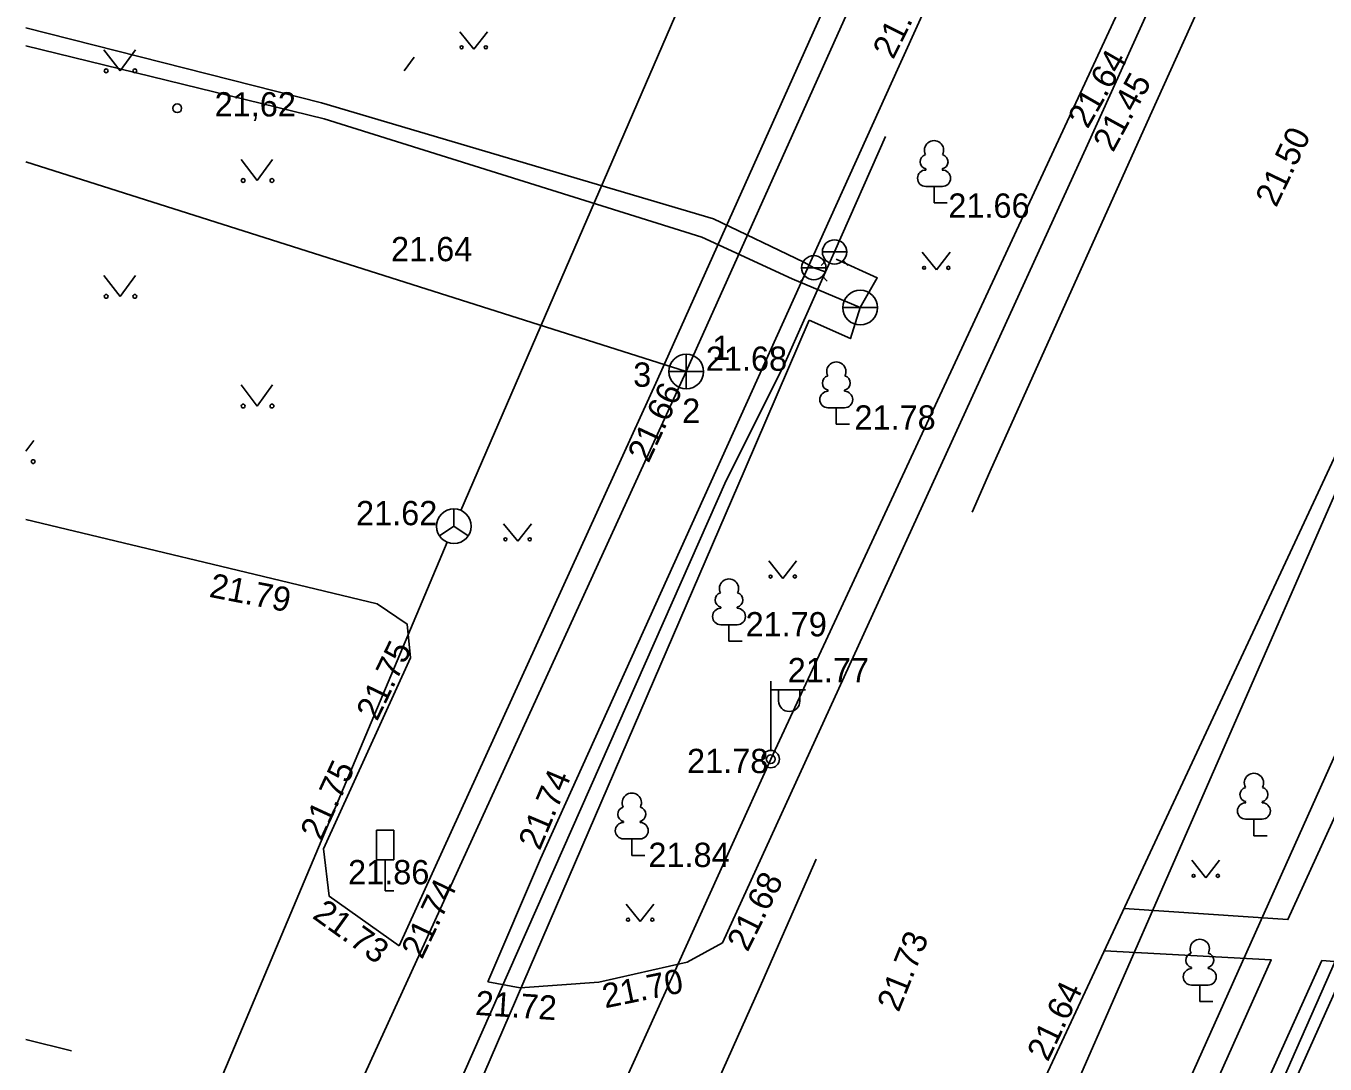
# Model space of a CAD drawing. Extents: x 714391 to 714584, y 6589993 to 6590151.
# Drawn here: x 714390.65 to 714428.09, y 6590022.48 to 6590052.39 of the extents above; entities that cross this region are included whole.
import ezdxf

# ---------------------------------------------------------------- set-up
doc = ezdxf.new("R2010")
doc.units = 0
for name, color, linetype in [('ABIJOONIS', 7, 'Continuous'), ('HALJASTUS', 7, 'Continuous'), ('HOONE', 7, 'Continuous'), ('KKAEV', 7, 'Continuous'), ('KORGUS', 7, 'Continuous'), ('KPKAABEL', 7, 'Continuous'), ('KTRASS', 7, 'Continuous'), ('LIIKLUS', 7, 'Continuous'), ('MPKAABEL', 7, 'Continuous'), ('POST', 7, 'Continuous'), ('PUU', 7, 'Continuous'), ('SIKAEV', 7, 'Continuous'), ('SITRASS', 7, 'Continuous'), ('SKTRASS', 7, 'Continuous'), ('TEE', 7, 'Continuous'), ('TORU NR', 7, 'Continuous'), ('VKAEV', 7, 'Continuous'), ('VTRASS', 7, 'Continuous'), ('По умолчанию', 7, 'Continuous'), ('Слой 1', 7, 'Continuous')]:
    doc.layers.add(name, color=color, linetype=linetype)

msp = doc.modelspace()

# ---------------------------------------------------------------- linework, layer by layer
at = {"layer": 'ABIJOONIS'}
for points in [[(714426.529, 6590057.51), (714423.049, 6590049.81), (714418.429, 6590039.54), (714417.917, 6590038.38)], [(714413.426, 6590028.381), (714411.78, 6590024.65), (714403.97, 6590007.22), (714397.447, 6589992.711)]]:
    msp.add_lwpolyline(points, dxfattribs=at)
at = {"layer": 'HALJASTUS'}
for p, q in [((714403.151, 6590052.228), (714403.556, 6590051.723)), ((714403.556, 6590051.723), (714403.951, 6590052.228)), ((714392.897, 6590051.707), (714393.36, 6590051.1)), ((714393.36, 6590051.1), (714393.806, 6590051.707)), ((714396.847, 6590048.547), (714397.31, 6590047.94)), ((714397.31, 6590047.94), (714397.756, 6590048.547)), ((714416.483, 6590045.873), (714416.888, 6590045.368)), ((714416.888, 6590045.368), (714417.283, 6590045.873)), ((714392.897, 6590045.207), (714393.36, 6590044.6)), ((714393.36, 6590044.6), (714393.806, 6590045.207)), ((714396.847, 6590042.047), (714397.31, 6590041.44)), ((714397.31, 6590041.44), (714397.756, 6590042.047)), ((714390.649, 6590040.139), (714390.876, 6590040.447)), ((714404.416, 6590038.05), (714404.821, 6590037.545)), ((714404.821, 6590037.545), (714405.216, 6590038.05)), ((714412.058, 6590036.978), (714412.463, 6590036.473)), ((714412.463, 6590036.473), (714412.858, 6590036.978)), ((714424.249, 6590028.353), (714424.654, 6590027.848)), ((714424.654, 6590027.848), (714425.049, 6590028.353)), ((714407.949, 6590027.089), (714408.354, 6590026.584)), ((714408.354, 6590026.584), (714408.749, 6590027.089))]:
    msp.add_line(p, q, dxfattribs=at)
for centre, radius in [((714403.203, 6590051.778), 0.0428), ((714403.903, 6590051.778), 0.0452), ((714392.959, 6590051.1), 0.055), ((714393.788, 6590051.1), 0.055), ((714396.909, 6590047.94), 0.055), ((714397.738, 6590047.94), 0.055), ((714416.535, 6590045.423), 0.0428), ((714417.235, 6590045.423), 0.0452), ((714392.959, 6590044.6), 0.055), ((714393.788, 6590044.6), 0.055), ((714396.909, 6590041.44), 0.055), ((714397.738, 6590041.44), 0.055), ((714390.858, 6590039.84), 0.055), ((714404.468, 6590037.6), 0.0428), ((714405.168, 6590037.6), 0.0452), ((714412.11, 6590036.528), 0.0428), ((714412.81, 6590036.528), 0.0452), ((714424.301, 6590027.903), 0.0428), ((714425.001, 6590027.903), 0.0452), ((714408.001, 6590026.639), 0.0428), ((714408.701, 6590026.639), 0.0452)]:
    msp.add_circle(centre, radius, dxfattribs=at)
at = {"layer": 'HOONE'}
msp.add_lwpolyline([(714459.73, 6590096.05), (714450.33, 6590074.44), (714440.46, 6590052.39), (714432.7, 6590035.24), (714421.56, 6590009.98), (714417.1, 6590000.12), (714413.783, 6589992.711)], dxfattribs=at)
at = {"layer": 'KKAEV'}
for p, q in [((714409.68, 6590041.935), (714409.68, 6590042.935)), ((714409.18, 6590042.435), (714410.18, 6590042.435))]:
    msp.add_line(p, q, dxfattribs=at)
msp.add_circle((714409.68, 6590042.435), 0.5, dxfattribs=at)
at = {"layer": 'KORGUS'}
msp.add_circle((714395.01, 6590050.02), 0.125, dxfattribs=at)
at = {"layer": 'KPKAABEL'}
msp.add_lwpolyline([(714390.649, 6590090.709), (714391.22, 6590087.72), (714411.651, 6590078.699), (714417.543, 6590076.021), (714419.18, 6590075.27), (714445.64, 6590069.88), (714433.16, 6590042.04), (714420.76, 6590014.4), (714410.92, 6589992.711)], dxfattribs=at)
at = {"layer": 'KTRASS'}
for p, q in [((714409.68, 6590042.435), (714419.428, 6590064.172)), ((714409.68, 6590042.435), (714390.649, 6590048.478)), ((714399.709, 6590020.666), (714409.68, 6590042.435))]:
    msp.add_line(p, q, dxfattribs=at)
at = {"layer": 'LIIKLUS'}
for p, q in [((714400.755, 6590029.218), (714400.755, 6590028.368)), ((714401.255, 6590029.218), (714400.755, 6590029.218)), ((714401.255, 6590029.218), (714401.255, 6590028.368)), ((714401.255, 6590028.368), (714400.755, 6590028.368)), ((714401.005, 6590028.368), (714401.005, 6590027.468)), ((714401.255, 6590027.468), (714401.005, 6590027.468))]:
    msp.add_line(p, q, dxfattribs=at)
at = {"layer": 'MPKAABEL'}
msp.add_lwpolyline([(714394.611, 6589992.711), (714400.19, 6590004.938), (714412.114, 6590031.265), (714423.696, 6590056.183), (714434.84, 6590082.35), (714435.599, 6590083.495), (714435.59, 6590083.97), (714441.1, 6590097.08), (714442.02, 6590098.72), (714442.75, 6590099.35), (714444.22, 6590100.41), (714445.54, 6590101.3), (714446.63, 6590102.41), (714450.168, 6590111.053), (714453.153, 6590116.846), (714463.66, 6590139.57), (714466.53, 6590147), (714468.444, 6590151.075)], dxfattribs=at)
at = {"layer": 'POST'}
for p, q in [((714412.114, 6590031.515), (714412.114, 6590033.515)), ((714412.114, 6590033.265), (714413.114, 6590033.265)), ((714412.341, 6590032.944), (714412.341, 6590033.265)), ((714412.953, 6590032.944), (714412.953, 6590033.265)), ((714412.114, 6590031.265), (714412.114, 6590031.265))]:
    msp.add_line(p, q, dxfattribs=at)
for radius in [0.25, 0.127]:
    msp.add_circle((714412.114, 6590031.265), radius, dxfattribs=at)
msp.add_arc((714412.647, 6590032.944), 0.306, 180, 0, dxfattribs=at)
at = {"layer": 'PUU'}
for p, q in [((714416.581, 6590048.272), (714416.581, 6590048.242)), ((714417.061, 6590048.272), (714417.061, 6590048.242)), ((714417.061, 6590047.767), (714416.581, 6590047.767)), ((714416.821, 6590047.292), (714416.821, 6590047.767)), ((714417.201, 6590047.292), (714416.821, 6590047.292)), ((714413.763, 6590041.895), (714413.763, 6590041.865)), ((714414.243, 6590041.895), (714414.243, 6590041.865)), ((714414.243, 6590041.39), (714413.763, 6590041.39)), ((714414.003, 6590040.915), (714414.003, 6590041.39)), ((714414.383, 6590040.915), (714414.003, 6590040.915)), ((714410.671, 6590035.643), (714410.671, 6590035.613)), ((714411.151, 6590035.643), (714411.151, 6590035.613)), ((714411.151, 6590035.138), (714410.671, 6590035.138)), ((714410.911, 6590034.663), (714410.911, 6590035.138)), ((714411.291, 6590034.663), (714410.911, 6590034.663)), ((714425.8, 6590030.04), (714425.8, 6590030.01)), ((714426.28, 6590030.04), (714426.28, 6590030.01)), ((714407.87, 6590029.471), (714407.87, 6590029.441)), ((714408.35, 6590029.471), (714408.35, 6590029.441)), ((714426.28, 6590029.535), (714425.8, 6590029.535)), ((714426.04, 6590029.06), (714426.04, 6590029.535)), ((714408.35, 6590028.966), (714407.87, 6590028.966)), ((714408.11, 6590028.491), (714408.11, 6590028.966)), ((714426.42, 6590029.06), (714426.04, 6590029.06)), ((714408.49, 6590028.491), (714408.11, 6590028.491)), ((714424.24, 6590025.26), (714424.24, 6590025.23)), ((714424.72, 6590025.26), (714424.72, 6590025.23)), ((714424.72, 6590024.755), (714424.24, 6590024.755)), ((714424.48, 6590024.28), (714424.48, 6590024.755)), ((714424.86, 6590024.28), (714424.48, 6590024.28))]:
    msp.add_line(p, q, dxfattribs=at)
for centre, radius, start, end in [((714416.821, 6590048.812), 0.277, 332.5799, 207.4201), ((714416.631, 6590048.48), 0.212, 105.2441, 257.079), ((714417.011, 6590048.48), 0.212, 282.921, 74.7559), ((714416.583, 6590048.005), 0.237, 90, 270), ((714417.058, 6590048.005), 0.237, 270, 90), ((714414.003, 6590042.435), 0.277, 332.5799, 207.4201), ((714413.813, 6590042.103), 0.212, 105.2441, 257.079), ((714414.193, 6590042.103), 0.212, 282.921, 74.7559), ((714413.765, 6590041.628), 0.237, 90, 270), ((714414.24, 6590041.628), 0.237, 270, 90), ((714410.911, 6590036.183), 0.277, 332.5799, 207.4201), ((714410.721, 6590035.851), 0.212, 105.2441, 257.079), ((714411.101, 6590035.851), 0.212, 282.921, 74.7559), ((714410.673, 6590035.376), 0.237, 90, 270), ((714411.149, 6590035.376), 0.237, 270, 90), ((714426.04, 6590030.58), 0.277, 332.5799, 207.4201), ((714425.85, 6590030.248), 0.212, 105.2441, 257.079), ((714426.23, 6590030.248), 0.212, 282.921, 74.7559), ((714408.11, 6590030.011), 0.277, 332.5799, 207.4201), ((714407.92, 6590029.679), 0.212, 105.2441, 257.079), ((714408.3, 6590029.679), 0.212, 282.921, 74.7559), ((714425.802, 6590029.773), 0.237, 90, 270), ((714426.277, 6590029.773), 0.237, 270, 90), ((714407.872, 6590029.204), 0.237, 90, 270), ((714408.347, 6590029.204), 0.237, 270, 90), ((714424.48, 6590025.8), 0.277, 332.5799, 207.4201), ((714424.29, 6590025.468), 0.212, 105.2441, 257.079), ((714424.67, 6590025.468), 0.212, 282.921, 74.7559), ((714424.242, 6590024.992), 0.237, 90, 270), ((714424.717, 6590024.992), 0.237, 270, 90)]:
    msp.add_arc(centre, radius, start, end, dxfattribs=at)
at = {"layer": 'SIKAEV'}
for p, q in [((714402.983, 6590038.476), (714402.983, 6590037.976)), ((714402.983, 6590037.976), (714402.568, 6590037.701)), ((714402.983, 6590037.976), (714403.398, 6590037.701))]:
    msp.add_line(p, q, dxfattribs=at)
msp.add_circle((714402.983, 6590037.976), 0.5, dxfattribs=at)
at = {"layer": 'SITRASS'}
for p, q in [((714428.828, 6590097.575), (714403.181, 6590038.435)), ((714402.789, 6590037.515), (714390.649, 6590008.74))]:
    msp.add_line(p, q, dxfattribs=at)
at = {"layer": 'SKTRASS'}
msp.add_line((714437.189, 6590059.042), (714419.801, 6590019.338), dxfattribs=at)
at = {"layer": 'TEE'}
for points in [[(714390.65, 6590124.59), (714396, 6590120.47), (714402.53, 6590115.27), (714412.65, 6590108.38), (714428.405, 6590098.635), (714430.062, 6590097.596), (714432.277, 6590096.218), (714432.498, 6590094.946), (714428.283, 6590085.404), (714423.452, 6590074.702), (714420.733, 6590068.851), (714418.831, 6590064.457), (714408.849, 6590042.202), (714401.401, 6590025.886)], [(714438.124, 6590086.085), (714427.962, 6590063.804), (714421.239, 6590048.97), (714410.72, 6590025.97)], [(714403.962, 6590024.844), (714405.48, 6590028.39), (714415.772, 6590051.14), (714422.922, 6590066.912)], [(714406.684, 6589992.711), (714411.807, 6590003.978), (714420.103, 6590022.258), (714430.572, 6590044.696), (714436.708, 6590058.068)], [(714430.249, 6590044.003), (714434.63, 6590043.29), (714427.02, 6590026.64), (714422.304, 6590026.966)], [(714396.74, 6590036.712), (714390.649, 6590038.175)], [(714396.74, 6590036.712), (714400.769, 6590035.743), (714401.632, 6590035.157), (714401.735, 6590034.181), (714399.222, 6590028.681), (714399.389, 6590027.313), (714401.401, 6590025.886)], [(714410.72, 6590025.97), (714409.701, 6590025.419), (714407.155, 6590024.843), (714404.892, 6590024.679), (714403.962, 6590024.844)], [(714421.729, 6590025.744), (714426.54, 6590025.48), (714416.12, 6590002.24), (714411.487, 6590003.275)], [(714457.41, 6590021.74), (714456.97, 6590022.09), (714456.24, 6590022.77), (714455.28, 6590023.03), (714451.04, 6590023.38), (714437.45, 6590024.7), (714430.368, 6590025.27), (714429.927, 6590025.305), (714428, 6590025.46), (714417.4, 6590001.98), (714418.881, 6590001.433), (714419.464, 6590001.218), (714420.84, 6590000.71), (714421.59, 6590000.94), (714422.12, 6590001.13), (714422.82, 6590001)], [(714390.649, 6590023.185), (714391.962, 6590022.859)]]:
    msp.add_lwpolyline(points, dxfattribs=at)
at = {"layer": 'VKAEV'}
for p, q in [((714413.603, 6590045.882), (714414.303, 6590045.882)), ((714413.005, 6590045.426), (714413.705, 6590045.426)), ((714413.706, 6590045.635), (714413.566, 6590045.495)), ((714414.2, 6590045.635), (714414.34, 6590045.495)), ((714413.108, 6590045.179), (714412.968, 6590045.039)), ((714413.602, 6590045.179), (714413.742, 6590045.039)), ((714414.192, 6590044.276), (714415.192, 6590044.276))]:
    msp.add_line(p, q, dxfattribs=at)
for centre, radius in [((714413.953, 6590045.882), 0.35), ((714413.355, 6590045.426), 0.35), ((714414.692, 6590044.276), 0.5)]:
    msp.add_circle(centre, radius, dxfattribs=at)
at = {"layer": 'VTRASS'}
for p, q in [((714399.241, 6590049.713), (714390.649, 6590051.825)), ((714410.131, 6590046.306), (714399.241, 6590049.713)), ((714412.735, 6590045.102), (714410.131, 6590046.306)), ((714413.953, 6590045.882), (714413.694, 6590045.309)), ((714413.694, 6590045.309), (714412.488, 6590042.613)), ((714414.692, 6590044.276), (714412.735, 6590045.102)), ((714412.488, 6590042.613), (714410.83, 6590039.297)), ((714410.83, 6590039.297), (714390.649, 6589993.74))]:
    msp.add_line(p, q, dxfattribs=at)
for points in [[(714390.649, 6590052.338), (714399.164, 6590050.177), (714410.466, 6590046.833), (714413.066, 6590045.588), (714413.355, 6590045.426), (714413.694, 6590045.309)], [(714413.953, 6590045.882), (714415.42, 6590049.21)], [(714413.224, 6590043.919), (714414.409, 6590043.383), (714414.692, 6590044.276), (714415.184, 6590045.135), (714413.999, 6590045.671)], [(714413.224, 6590043.919), (714411.375, 6590039.633), (714401.025, 6590015.647), (714390.649, 6589994.119)]]:
    msp.add_lwpolyline(points, dxfattribs=at)
at = {"layer": 'По умолчанию'}
msp.add_line((714401.55, 6590051.1), (714401.837, 6590051.491), dxfattribs=at)
at = {"layer": 'Слой 1'}
msp.add_lwpolyline([(714455.78, 6590085.63), (714478.99, 6590085.97), (714478.28, 6590068.22), (714475.39, 6590009.54), (714423.1, 6590012.8)], close=True, dxfattribs=at)

# ---------------------------------------------------------------- texts
at = {"layer": 'KORGUS'}
for s, rotation, p in [('21.58', 63.4349, (714415.645, 6590051.403)), ('21.64', 60.124, (714421.247, 6590049.405)), ('21.45', 61.3611, (714421.98, 6590048.728)), ('21.50', 64.3978, (714426.681, 6590047.139)), ('21.66', 64.9228, (714408.592, 6590039.773)), ('21.79', 348.9365, (714395.903, 6590035.946)), ('21.75', 64.3281, (714400.768, 6590032.337)), ('21.75', 65.2249, (714399.16, 6590028.885)), ('21.74', 67.0459, (714405.456, 6590028.608)), ('21.68', 63.6048, (714411.448, 6590025.684)), ('21.74', 64.3684, (714402.066, 6590025.474)), ('21.73', 324.2461, (714398.873, 6590026.706)), ('21.73', 68.0661, (714415.801, 6590023.95)), ('21.70', 11.5187, (714407.34, 6590024.084)), ('21.64', 64.3382, (714420.1, 6590022.521)), ('21.72', 356.2277, (714403.584, 6590023.898))]:
    msp.add_text(s, height=0.7, rotation=rotation, dxfattribs=at).set_placement(p)
for s, p in [('21,62', (714396.086, 6590049.785)), ('21.66', (714417.232, 6590046.867)), ('21.64', (714401.171, 6590045.614)), ('21.68', (714410.243, 6590042.456)), ('21.78', (714414.526, 6590040.761)), ('21.62', (714400.162, 6590038.006)), ('21.79', (714411.389, 6590034.803)), ('21.77', (714412.604, 6590033.482)), ('21.78', (714409.702, 6590030.863)), ('21.84', (714408.588, 6590028.157)), ('21.86', (714399.933, 6590027.659))]:
    msp.add_text(s, height=0.7, dxfattribs=at).set_placement(p)
at = {"layer": 'TORU NR'}
for s, p in [('1', (714410.431, 6590042.771)), ('3', (714408.15, 6590041.996)), ('2', (714409.561, 6590040.956))]:
    msp.add_text(s, height=0.7, dxfattribs=at).set_placement(p)

doc.saveas('drawing.dxf')
